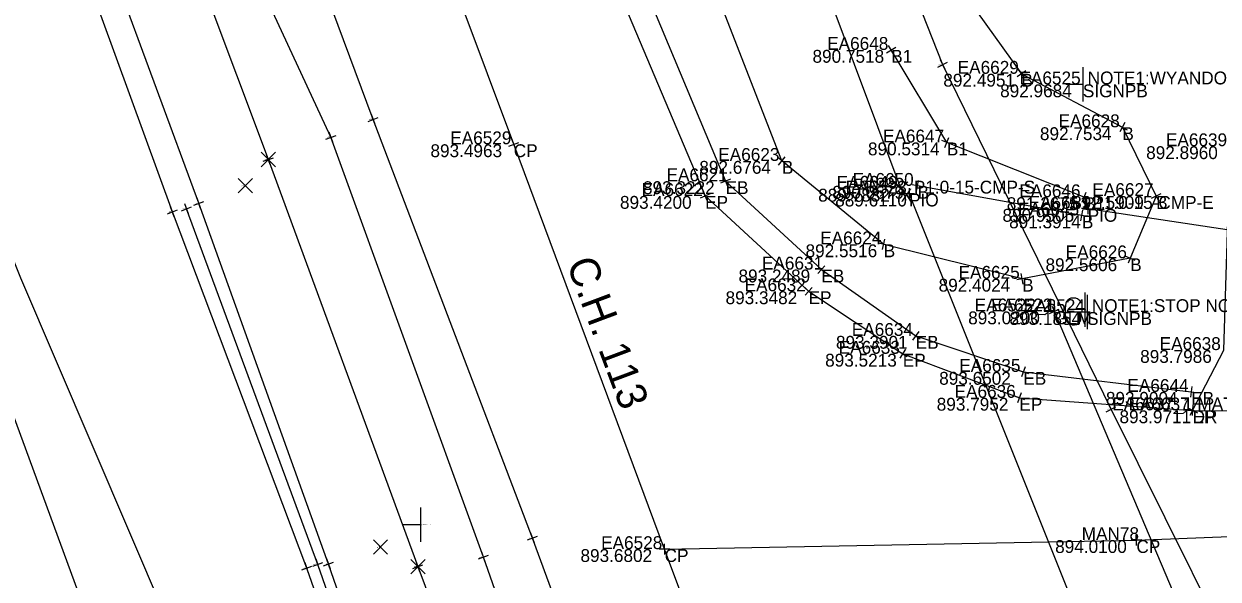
# Model space of a CAD drawing. Extents: x 179044 to 189691, y 286531 to 301257.
# Drawn here: x 180327.9 to 180439.4, y 300591.3 to 300643.1 of the extents above; entities that cross this region are included whole.
import ezdxf

# ---------------------------------------------------------------- set-up
doc = ezdxf.new("R2010")
doc.units = 0
for name, color, linetype in [('Default', 7, 'Continuous'), ('DR_X_Ditch', 7, 'Continuous'), ('DR_X_Elev_Flow', 7, 'Continuous'), ('DR_X_Storm_Sewer', 7, 'Continuous'), ('PV_X_COP', 7, 'Continuous'), ('PV_X_Driveway', 7, 'Continuous'), ('PV_X_EOP', 7, 'Continuous'), ('PV_X_Shoulder_Aggregate', 7, 'Continuous'), ('RD_X_Fence', 7, 'Continuous'), ('SN_X_Public', 7, 'Continuous'), ('SV_X_Break_Lines', 7, 'Continuous'), ('SV_X_Random_Point', 7, 'Continuous'), ('SV_X_Shot_Marker', 7, 'Continuous'), ('SV_X_Text_Comment', 7, 'Continuous'), ('SV_X_Text_Description', 7, 'Continuous'), ('SV_X_Text_Elevation', 7, 'Continuous'), ('SV_X_Text_Name', 7, 'Continuous'), ('SV_X_Toe_of_Slope', 7, 'Continuous'), ('SV_X_Top_of_Bank', 7, 'Continuous'), ('UT_X_Gas', 7, 'Continuous'), ('UT_X_Gas_Cells', 7, 'Continuous')]:
    doc.layers.add(name, color=color, linetype=linetype)

msp = doc.modelspace()

# ---------------------------------------------------------------- linework, layer by layer
at = {"layer": 'DR_X_Ditch'}
msp.add_lwpolyline([(180378.56, 300526.19), (180366.86, 300559.54), (180355.31, 300592.64), (180343.05, 300625.83)], dxfattribs=at)
at = {"layer": 'DR_X_Elev_Flow'}
for p, q in [((180410.03, 300627.25), (180411.03, 300627.25)), ((180410.5, 300627.25), (180410.55, 300627.25)), ((180410.53, 300627.75), (180410.53, 300626.75)), ((180410.53, 300627.27), (180410.53, 300627.22)), ((180410.53, 300627.25), (180410.53, 300627.25)), ((180410.53, 300627.25), (180410.53, 300627.25)), ((180427.21, 300626.32), (180427.21, 300625.32)), ((180426.71, 300625.82), (180427.71, 300625.82)), ((180427.19, 300625.82), (180427.24, 300625.82)), ((180427.21, 300625.85), (180427.21, 300625.8)), ((180427.21, 300625.82), (180427.21, 300625.82)), ((180427.21, 300625.82), (180427.21, 300625.82))]:
    msp.add_line(p, q, dxfattribs=at)
at = {"layer": 'DR_X_Storm_Sewer'}
for p, q in [((180442.64, 300547.08), (180410.53, 300627.25)), ((180454.87, 300621.65), (180427.21, 300625.82))]:
    msp.add_line(p, q, dxfattribs=at)
at = {"layer": 'PV_X_COP'}
for points in [[(180435.29, 300467.37), (180412.88, 300528.12), (180394.43, 300576.01), (180387.7, 300594.07), (180373.61, 300631.85), (180356.6, 300677.34), (180322.12, 300769.7)], [(180387.7, 300594.07), (180431.76, 300594.91), (180492.59, 300597.31)]]:
    msp.add_lwpolyline(points, dxfattribs=at)
at = {"layer": 'PV_X_Driveway'}
msp.add_lwpolyline([(180437.01, 300607.02), (180439.92, 300612.65), (180440.51, 300631.67), (180452.7, 300630.12), (180451.25, 300618.3), (180450.77, 300610.79), (180453.78, 300606.87)], dxfattribs=at)
at = {"layer": 'PV_X_EOP'}
for points in [[(180336.02, 300768.96), (180371.12, 300675.18), (180391.48, 300627.03), (180401.14, 300618.13), (180409.94, 300612.3), (180420.83, 300608.19), (180437.01, 300607.02), (180453.78, 300606.87), (180491.75, 300607.1)], [(180395.24, 300541.25), (180387.76, 300561.4), (180375.37, 300595.1), (180360.49, 300634.17), (180345.73, 300673.8)], [(180354.79, 300532.59), (180349.9, 300545.54), (180346.76, 300553.04), (180334.48, 300585.86), (180323, 300617.06), (180321.27, 300620.87), (180302.72, 300670.75)]]:
    msp.add_lwpolyline(points, dxfattribs=at)
at = {"layer": 'PV_X_Shoulder_Aggregate'}
msp.add_lwpolyline([(180337.75, 300769.37), (180373.5, 300675.95), (180393.39, 300628.4), (180402.34, 300620.16), (180411.15, 300613.97), (180421.2, 300610.61), (180436.88, 300608.74)], dxfattribs=at)
at = {"layer": 'RD_X_Fence'}
msp.add_lwpolyline([(180399.73, 300496.44), (180388.78, 300528.13), (180377.77, 300557.4), (180364.67, 300592.43), (180350.69, 300630.43), (180323.97, 300701.53)], dxfattribs=at)
at = {"layer": 'SN_X_Public'}
for p, q in [((180426.76, 300639.04), (180426.76, 300635.84)), ((180426.76, 300637.44), (180425.16, 300637.44)), ((180426.94, 300618.02), (180426.94, 300614.82)), ((180427.15, 300617.79), (180427.15, 300614.59)), ((180426.94, 300616.42), (180425.34, 300616.42)), ((180427.15, 300616.19), (180425.55, 300616.19)), ((180364.89, 300597.95), (180364.89, 300594.75)), ((180364.89, 300596.35), (180363.29, 300596.35))]:
    msp.add_line(p, q, dxfattribs=at)
at = {"layer": 'SV_X_Break_Lines'}
for points in [[(180355.21, 300773.19), (180388.06, 300685.64), (180409.75, 300627.7)], [(180415.96, 300645.51), (180421.02, 300638.43), (180430.45, 300633.44), (180433.6, 300627.02), (180431.18, 300621.21), (180421.09, 300619.3), (180408.16, 300622.51), (180398.65, 300630.3), (180379.34, 300679.91), (180346.83, 300771.37)], [(180426.88, 300626.91), (180414.06, 300632.02), (180408.86, 300640.66)], [(180426.67, 300625.21), (180411.32, 300627.97)]]:
    msp.add_lwpolyline(points, dxfattribs=at)
at = {"layer": 'SV_X_Random_Point'}
for p, q in [((180350.02, 300629.76), (180351.35, 300631.1)), ((180350.02, 300631.1), (180351.35, 300629.76)), ((180347.88, 300627.32), (180349.21, 300628.66)), ((180347.88, 300628.66), (180349.21, 300627.32)), ((180409.08, 300627.03), (180410.41, 300628.36)), ((180409.08, 300628.36), (180410.41, 300627.03)), ((180360.5, 300593.6), (180361.83, 300594.94)), ((180360.5, 300594.94), (180361.83, 300593.6)), ((180364, 300591.76), (180365.33, 300593.1)), ((180364, 300593.1), (180365.33, 300591.76))]:
    msp.add_line(p, q, dxfattribs=at)
at = {"layer": 'SV_X_Shot_Marker'}
for p, q in [((180408.43, 300640.4), (180409.29, 300640.91)), ((180409.12, 300640.23), (180408.6, 300641.08)), ((180408.86, 300640.66), (180408.86, 300640.66)), ((180413.89, 300638.83), (180413.45, 300639.73)), ((180413.22, 300639.06), (180414.12, 300639.5)), ((180413.67, 300639.28), (180413.67, 300639.28)), ((180421.43, 300638.72), (180420.61, 300638.14)), ((180420.73, 300638.83), (180421.31, 300638.02)), ((180421.02, 300638.43), (180421.02, 300638.43)), ((180360.02, 300633.99), (180360.96, 300634.35)), ((180360.67, 300633.7), (180360.31, 300634.64)), ((180360.49, 300634.17), (180360.49, 300634.17)), ((180356.71, 300632.04), (180356.37, 300632.98)), ((180430, 300633.68), (180430.89, 300633.21)), ((180430.68, 300633.88), (180430.21, 300633)), ((180430.45, 300633.44), (180430.45, 300633.44)), ((180356.07, 300632.34), (180357.01, 300632.68)), ((180356.54, 300632.51), (180356.54, 300632.51)), ((180373.15, 300631.67), (180374.08, 300632.02)), ((180373.79, 300631.38), (180373.44, 300632.32)), ((180373.61, 300631.85), (180373.61, 300631.85)), ((180414.53, 300631.84), (180413.6, 300632.21)), ((180413.88, 300631.56), (180414.25, 300632.48)), ((180414.06, 300632.02), (180414.06, 300632.02)), ((180350.22, 300630.26), (180351.16, 300630.6)), ((180350.86, 300629.96), (180350.51, 300630.9)), ((180399.04, 300629.98), (180398.26, 300630.61)), ((180398.33, 300629.91), (180398.97, 300630.68)), ((180350.69, 300630.43), (180350.69, 300630.43)), ((180398.65, 300630.3), (180398.65, 300630.3)), ((180393.85, 300628.6), (180392.92, 300628.21)), ((180393.19, 300628.86), (180393.58, 300627.94)), ((180393.39, 300628.4), (180393.39, 300628.4)), ((180411.23, 300627.48), (180411.41, 300628.47)), ((180391.28, 300627.49), (180391.67, 300626.57)), ((180411.81, 300627.89), (180410.83, 300628.06)), ((180411.32, 300627.97), (180411.32, 300627.97)), ((180426.69, 300626.45), (180427.06, 300627.38)), ((180434.05, 300627.24), (180433.15, 300626.8)), ((180433.38, 300627.47), (180433.82, 300626.57)), ((180343.23, 300625.36), (180342.88, 300626.3)), ((180343.73, 300626.17), (180344.67, 300626.51)), ((180344.37, 300625.87), (180344.03, 300626.81)), ((180344.2, 300626.34), (180344.2, 300626.34)), ((180391.94, 300627.22), (180391.02, 300626.83)), ((180391.48, 300627.03), (180391.48, 300627.03)), ((180427.34, 300626.73), (180426.41, 300627.1)), ((180426.88, 300626.91), (180426.88, 300626.91)), ((180433.6, 300627.02), (180433.6, 300627.02)), ((180341.26, 300625.37), (180342.2, 300625.72)), ((180341.91, 300625.08), (180341.56, 300626.01)), ((180341.73, 300625.55), (180341.73, 300625.55)), ((180342.58, 300625.65), (180343.52, 300626)), ((180343.05, 300625.83), (180343.05, 300625.83)), ((180427.16, 300625.12), (180426.18, 300625.3)), ((180426.58, 300624.72), (180426.76, 300625.7)), ((180426.67, 300625.21), (180426.67, 300625.21)), ((180408.04, 300622.02), (180408.28, 300622.99)), ((180408.64, 300622.39), (180407.67, 300622.63)), ((180408.16, 300622.51), (180408.16, 300622.51)), ((180431.37, 300621.67), (180430.99, 300620.75)), ((180431.64, 300621.02), (180430.72, 300621.4)), ((180431.18, 300621.21), (180431.18, 300621.21)), ((180401.97, 300620.5), (180402.7, 300619.82)), ((180402.67, 300620.52), (180402, 300619.79)), ((180402.34, 300620.16), (180402.34, 300620.16)), ((180421.18, 300618.81), (180421, 300619.79)), ((180400.78, 300618.47), (180401.51, 300617.79)), ((180401.48, 300618.49), (180400.81, 300617.76)), ((180421.58, 300619.39), (180420.6, 300619.21)), ((180421.09, 300619.3), (180421.09, 300619.3)), ((180401.14, 300618.13), (180401.14, 300618.13)), ((180423.64, 300616.06), (180424.56, 300616.45)), ((180424.3, 300615.79), (180423.91, 300616.71)), ((180424.1, 300616.25), (180424.1, 300616.25)), ((180410.74, 300614.25), (180411.56, 300613.68)), ((180411.44, 300614.38), (180410.86, 300613.56)), ((180411.15, 300613.97), (180411.15, 300613.97)), ((180409.52, 300612.58), (180410.35, 300612.03)), ((180410.21, 300612.72), (180409.66, 300611.89)), ((180409.94, 300612.3), (180409.94, 300612.3)), ((180420.72, 300610.77), (180421.67, 300610.45)), ((180421.36, 300611.09), (180421.04, 300610.14)), ((180421.2, 300610.61), (180421.2, 300610.61)), ((180420.37, 300608.37), (180421.3, 300608.02)), ((180421.01, 300608.66), (180420.66, 300607.73)), ((180436.39, 300608.8), (180437.38, 300608.68)), ((180436.94, 300609.24), (180436.82, 300608.24)), ((180436.88, 300608.74), (180436.88, 300608.74)), ((180420.83, 300608.19), (180420.83, 300608.19)), ((180428.95, 300606.89), (180429.85, 300607.34)), ((180429.62, 300606.67), (180429.18, 300607.56)), ((180436.56, 300607.25), (180437.45, 300606.79)), ((180436.78, 300606.58), (180437.24, 300607.47)), ((180437.04, 300607.52), (180436.97, 300606.53)), ((180429.4, 300607.12), (180429.4, 300607.12)), ((180436.51, 300607.06), (180437.51, 300606.99)), ((180437.01, 300607.02), (180437.01, 300607.02)), ((180437.01, 300607.02), (180437.01, 300607.02)), ((180374.9, 300594.93), (180375.84, 300595.27)), ((180375.54, 300594.63), (180375.19, 300595.57)), ((180375.37, 300595.1), (180375.37, 300595.1)), ((180432.26, 300594.93), (180431.26, 300594.89)), ((180431.78, 300594.41), (180431.74, 300595.41)), ((180431.76, 300594.91), (180431.76, 300594.91)), ((180370.95, 300592.85), (180370.62, 300593.8)), ((180388.2, 300594.08), (180387.2, 300594.06)), ((180387.71, 300593.57), (180387.69, 300594.57)), ((180387.7, 300594.07), (180387.7, 300594.07)), ((180354.45, 300591.83), (180354.12, 300592.78)), ((180354.84, 300592.48), (180355.78, 300592.81)), ((180355.48, 300592.17), (180355.15, 300593.12)), ((180355.84, 300592.51), (180356.78, 300592.84)), ((180356.48, 300592.2), (180356.15, 300593.15)), ((180356.31, 300592.68), (180356.31, 300592.68)), ((180364.84, 300591.96), (180364.49, 300592.9)), ((180370.32, 300593.16), (180371.26, 300593.49)), ((180370.79, 300593.33), (180370.79, 300593.33)), ((180353.81, 300592.14), (180354.76, 300592.47)), ((180354.28, 300592.3), (180354.28, 300592.3)), ((180355.31, 300592.64), (180355.31, 300592.64)), ((180364.2, 300592.26), (180365.13, 300592.61)), ((180364.67, 300592.43), (180364.67, 300592.43))]:
    msp.add_line(p, q, dxfattribs=at)
at = {"layer": 'SV_X_Toe_of_Slope'}
for points in [[(180389.99, 300492.48), (180377.03, 300526.61), (180365.84, 300559.26), (180354.28, 300592.3), (180341.73, 300625.55), (180325.91, 300668.93)], [(180391.24, 300493.14), (180379.39, 300526.41), (180367.71, 300559.94), (180356.31, 300592.68), (180344.2, 300626.34), (180328.4, 300669.2)]]:
    msp.add_lwpolyline(points, dxfattribs=at)
at = {"layer": 'SV_X_Top_of_Bank'}
for points in [[(180397.95, 300519.64), (180393.37, 300530.61), (180382.9, 300558.8), (180370.79, 300593.33), (180356.54, 300632.51), (180338.25, 300671.9)], [(180374.35, 300486.27), (180360.91, 300530.13), (180353.69, 300554.64), (180341.1, 300587.8), (180327.58, 300619.35), (180306.58, 300671.81)]]:
    msp.add_lwpolyline(points, dxfattribs=at)
at = {"layer": 'UT_X_Gas'}
for points in [[(180490.47, 300448.38), (180476.39, 300497.95), (180471.56, 300513.1), (180457.1, 300544.93), (180444.55, 300576.64), (180429.4, 300607.12), (180413.67, 300639.28), (180388.52, 300702.94)], [(180481.27, 300481.02), (180458.12, 300535.95), (180424.1, 300616.25)]]:
    msp.add_lwpolyline(points, dxfattribs=at)
at = {"layer": 'UT_X_Gas_Cells'}
for p, q in [((180424.1, 300615.25), (180424.1, 300617.25)), ((180424.1, 300616.25), (180423.15, 300616.25))]:
    msp.add_line(p, q, dxfattribs=at)
msp.add_lwpolyline([(180426.58, 300617.01), (180426.56, 300617.11), (180426.5, 300617.21), (180426.4, 300617.3), (180426.26, 300617.42), (180426.17, 300617.46), (180426.09, 300617.48), (180425.97, 300617.5), (180425.73, 300617.5), (180425.63, 300617.48), (180425.58, 300617.46), (180425.5, 300617.42), (180425.34, 300617.3), (180425.24, 300617.17), (180425.18, 300617.01), (180425.14, 300616.79), (180425.1, 300616.48), (180425.1, 300616.06), (180425.12, 300615.73), (180425.2, 300615.47), (180425.32, 300615.24), (180425.42, 300615.16), (180425.54, 300615.08), (180425.75, 300615), (180425.97, 300615), (180426.19, 300615.04), (180426.26, 300615.08), (180426.34, 300615.12), (180426.42, 300615.2), (180426.5, 300615.32), (180426.58, 300615.49), (180426.58, 300615.99), (180426.17, 300615.99)], dxfattribs=at)

# ---------------------------------------------------------------- texts
at = {"layer": 'Default'}
msp.add_text('C.H. 113', height=2.8, rotation=290.4535, dxfattribs=at).set_placement((180378.51, 300620.73))
at = {"layer": 'SV_X_Text_Comment'}
for s, height, p in [('B1', 1.2, (180408.86, 300639.46)), ('GL', 0.06, (180413.67, 300639.22)), ('B', 1.2, (180421.02, 300637.23)), ('SIGNPB', 1.2, (180426.76, 300636.24)), ('EP', 0.06, (180360.49, 300634.11)), ('B', 1.2, (180430.45, 300632.24)), ('TB', 0.06, (180356.54, 300632.45)), ('CP', 1.2, (180373.61, 300630.65)), ('B1', 1.2, (180414.06, 300630.82)), ('FEN', 0.06, (180350.69, 300630.37)), ('X', 0.06, (180350.69, 300630.37)), ('B', 1.2, (180398.65, 300629.1)), ('EB', 1.2, (180393.39, 300627.2)), ('X', 0.06, (180348.55, 300627.93)), ('X', 1.2, (180409.75, 300626.5)), ('P1=0-15-CMP-S', 0.06, (180410.53, 300627.19)), ('PIO', 1.2, (180410.53, 300626.05)), ('B', 1.2, (180411.32, 300626.77)), ('TSL', 0.06, (180344.2, 300626.28)), ('EP', 1.2, (180391.48, 300625.83)), ('B1', 1.2, (180426.88, 300625.71)), ('B', 1.2, (180433.6, 300625.82)), ('TSL1', 0.06, (180341.73, 300625.49)), ('D', 0.06, (180343.05, 300625.77)), ('B', 1.2, (180426.67, 300624.01)), ('P1=0-15-CMP-E', 0.06, (180427.21, 300625.76)), ('PIO', 1.2, (180427.21, 300624.62)), ('B', 1.2, (180408.16, 300621.31)), ('B', 1.2, (180431.18, 300620.01)), ('EB', 1.2, (180402.34, 300618.96)), ('B', 1.2, (180421.09, 300618.1)), ('EP', 1.2, (180401.14, 300616.93)), ('GLM', 1.2, (180424.1, 300615.05)), ('GL', 1.2, (180424.1, 300615.05)), ('SIGNPB', 0.06, (180426.94, 300616.36)), ('SIGNPB', 1.2, (180427.15, 300614.99)), ('EB', 1.2, (180411.15, 300612.77)), ('EP', 1.2, (180409.94, 300611.1)), ('EB', 1.2, (180421.2, 300609.41)), ('EB', 1.2, (180436.88, 300607.54)), ('EP', 1.2, (180420.83, 300606.99)), ('GL', 0.06, (180429.4, 300607.06)), ('EP', 1.2, (180437.01, 300605.82)), ('DR', 1.2, (180437.01, 300605.82)), ('SIGNPB', 0.06, (180364.89, 300596.29)), ('EP', 0.06, (180375.37, 300595.04)), ('CP', 1.2, (180431.76, 300593.71)), ('X', 0.06, (180361.17, 300594.21)), ('CP', 1.2, (180387.7, 300592.87)), ('TSL', 0.06, (180356.31, 300592.62)), ('TB', 0.06, (180370.79, 300593.27)), ('TSL1', 0.06, (180354.28, 300592.24)), ('D', 0.06, (180355.31, 300592.58)), ('X', 0.06, (180364.67, 300592.37)), ('FEN', 0.06, (180364.67, 300592.37))]:
    msp.add_text(s, height=height, dxfattribs=at).set_placement(p)
at = {"layer": 'SV_X_Text_Description'}
for s, height, p in [(' NOTE1:WYANDOT CH 113 NOTE2:WYANDOT CH 62', 1.2, (180426.76, 300637.44)), (' P1:0-15-CMP-S', 1.2, (180410.53, 300627.25)), ('P1= 0-15-CMP-S', 0.06, (180410.53, 300627.25)), (' P1:0-15-CMP-E', 1.2, (180427.21, 300625.82)), ('P1= 0-15-CMP-E', 0.06, (180427.21, 300625.82)), (' NOTE1:STOP NOTE2:CROSS TRAFFIC DOES NOT STOP', 1.2, (180427.15, 300616.19)), (' NOTE:STOP', 0.06, (180426.94, 300616.42)), (' MATERIAL:ASPHALT TYPE:OTHER', 1.2, (180437.01, 300607.02)), (' MATERIAL:ASPHALT TYPE:OTHER', 1.2, (180437.01, 300607.02)), (' NOTE:DOUBLE ARROW', 0.06, (180364.89, 300596.35))]:
    msp.add_text(s, height=height, dxfattribs=at).set_placement(p)
at = {"layer": 'SV_X_Text_Elevation'}
for s, height, p in [('890.7518', 1.2, (180401.51, 300639.46)), ('891.4520', 0.06, (180413.3, 300639.22)), ('892.4951', 1.2, (180413.73, 300637.23)), ('892.9684', 1.2, (180419.03, 300636.24)), ('893.2700', 0.06, (180360.1, 300634.11)), ('892.7534', 1.2, (180422.75, 300632.24)), ('892.8160', 0.06, (180356.17, 300632.45)), ('893.4963', 1.2, (180365.83, 300630.65)), ('890.5314', 1.2, (180406.69, 300630.82)), ('892.8960', 1.2, (180432.67, 300630.47)), ('892.1350', 0.06, (180350.32, 300630.37)), ('892.1350', 0.06, (180350.32, 300630.37)), ('892.6764', 1.2, (180390.94, 300629.1)), ('893.3222', 1.2, (180385.68, 300627.2)), ('891.4460', 0.06, (180348.18, 300627.93)), ('889.7832', 1.2, (180402.04, 300626.5)), ('890.0679', 1.2, (180403.36, 300626.77)), ('889.6110', 1.2, (180403.63, 300626.05)), ('889.61', 0.06, (180410.27, 300627.19)), ('890.1920', 0.06, (180343.83, 300626.28)), ('893.4200', 1.2, (180383.53, 300625.83)), ('891.2675', 1.2, (180419.65, 300625.71)), ('892.5909', 1.2, (180425.76, 300625.82)), ('890.1820', 0.06, (180341.36, 300625.49)), ('890.0750', 0.06, (180342.65, 300625.77)), ('890.9505', 1.2, (180419.25, 300624.62)), ('891.3914', 1.2, (180419.87, 300624.01)), ('890.95', 0.06, (180426.93, 300625.76)), ('892.5516', 1.2, (180400.86, 300621.31)), ('892.5606', 1.2, (180423.27, 300620.01)), ('893.2489', 1.2, (180394.6, 300618.96)), ('892.4024', 1.2, (180413.29, 300618.1)), ('893.3482', 1.2, (180393.39, 300616.93)), ('893.0200', 1.2, (180416.05, 300615.05)), ('893.0200', 1.2, (180416.05, 300615.05)), ('893.1854', 1.2, (180419.9, 300614.99)), ('892.9340', 0.06, (180426.55, 300616.36)), ('893.3901', 1.2, (180403.7, 300612.77)), ('893.5213', 1.2, (180402.69, 300611.1)), ('893.7986', 1.2, (180432.11, 300611.45)), ('893.6502', 1.2, (180413.34, 300609.41)), ('893.9004', 1.2, (180428.91, 300607.54)), ('893.7952', 1.2, (180413.11, 300606.99)), ('893.8470', 0.06, (180429.01, 300607.06)), ('893.9711', 1.2, (180430.18, 300605.82)), ('893.9711', 1.2, (180430.18, 300605.82)), ('892.4950', 0.06, (180364.5, 300596.29)), ('893.4470', 0.06, (180374.97, 300595.04)), ('894.0100', 1.2, (180424.17, 300593.71)), ('891.5450', 0.06, (180360.8, 300594.21)), ('893.6802', 1.2, (180379.84, 300592.87)), ('890.2290', 0.06, (180355.92, 300592.62)), ('892.8670', 0.06, (180370.4, 300593.27)), ('890.2020', 0.06, (180353.88, 300592.24)), ('890.0900', 0.06, (180354.9, 300592.58)), ('892.1630', 0.06, (180364.3, 300592.37)), ('892.1630', 0.06, (180364.3, 300592.37))]:
    msp.add_text(s, height=height, dxfattribs=at).set_placement(p)
at = {"layer": 'SV_X_Text_Name'}
for s, height, p in [('EA6648', 1.2, (180402.88, 300640.66)), ('EA6629', 1.2, (180415.07, 300638.43)), ('SV5042', 0.06, (180413.37, 300639.28)), ('EA6525', 1.2, (180420.84, 300637.44)), ('SV5097', 0.06, (180360.19, 300634.17)), ('EA6628', 1.2, (180424.49, 300633.44)), ('EA6529', 1.2, (180367.68, 300631.85)), ('EA6647', 1.2, (180408.09, 300632.02)), ('EA6639', 1.2, (180434.52, 300631.67)), ('SV5098', 0.06, (180356.24, 300632.51)), ('EA6623', 1.2, (180392.71, 300630.3)), ('SV5099_1', 0.06, (180350.32, 300630.43)), ('SV5099', 0.06, (180350.38, 300630.43)), ('EA6621', 1.2, (180387.88, 300628.4)), ('EA6649', 1.2, (180403.76, 300627.7)), ('EA6523', 1.2, (180404.6, 300627.25)), ('EA6650', 1.2, (180405.25, 300627.97)), ('SV5126', 0.06, (180348.27, 300627.99)), ('EA6622', 1.2, (180385.55, 300627.03)), ('EA6523', 0.06, (180410.23, 300627.25)), ('EA6646', 1.2, (180420.83, 300626.91)), ('EA6627', 1.2, (180427.65, 300627.02)), ('SV5125', 0.06, (180343.93, 300626.34)), ('EA6645', 1.2, (180420.7, 300625.21)), ('EA6651', 1.2, (180421.69, 300625.82)), ('SV5123', 0.06, (180341.46, 300625.55)), ('SV5124', 0.06, (180342.78, 300625.83)), ('EA6651', 0.06, (180426.94, 300625.82)), ('EA6624', 1.2, (180402.23, 300622.51)), ('EA6626', 1.2, (180425.16, 300621.21)), ('EA6631', 1.2, (180396.79, 300620.16)), ('EA6625', 1.2, (180415.15, 300619.3)), ('EA6632', 1.2, (180395.17, 300618.13)), ('EA6522_1', 1.2, (180416.66, 300616.25)), ('EA6522', 1.2, (180418.19, 300616.25)), ('EA6524', 1.2, (180421.24, 300616.19)), ('SV5041', 0.06, (180426.67, 300616.42)), ('EA6634', 1.2, (180405.18, 300613.97)), ('EA6638', 1.2, (180433.93, 300612.65)), ('EA6633', 1.2, (180403.96, 300612.3)), ('EA6635', 1.2, (180415.22, 300610.61)), ('EA6636', 1.2, (180414.78, 300608.19)), ('EA6644', 1.2, (180430.92, 300608.74)), ('SV5040', 0.06, (180429.09, 300607.12)), ('EA6637_1', 1.2, (180429.51, 300607.02)), ('EA6637', 1.2, (180431.03, 300607.02)), ('SV5088', 0.06, (180364.59, 300596.35)), ('MAN78', 1.2, (180426.65, 300594.91)), ('SV5096', 0.06, (180375.06, 300595.1)), ('EA6528', 1.2, (180381.77, 300594.07)), ('SV5113', 0.06, (180360.92, 300594.27)), ('SV5115', 0.06, (180355.06, 300592.64)), ('SV5114', 0.06, (180356.06, 300592.68)), ('SV5095', 0.06, (180370.48, 300593.33)), ('SV5116', 0.06, (180354.03, 300592.3)), ('SV5094_1', 0.06, (180364.3, 300592.43)), ('SV5094', 0.06, (180364.36, 300592.43))]:
    msp.add_text(s, height=height, dxfattribs=at).set_placement(p)

doc.saveas('drawing.dxf')
